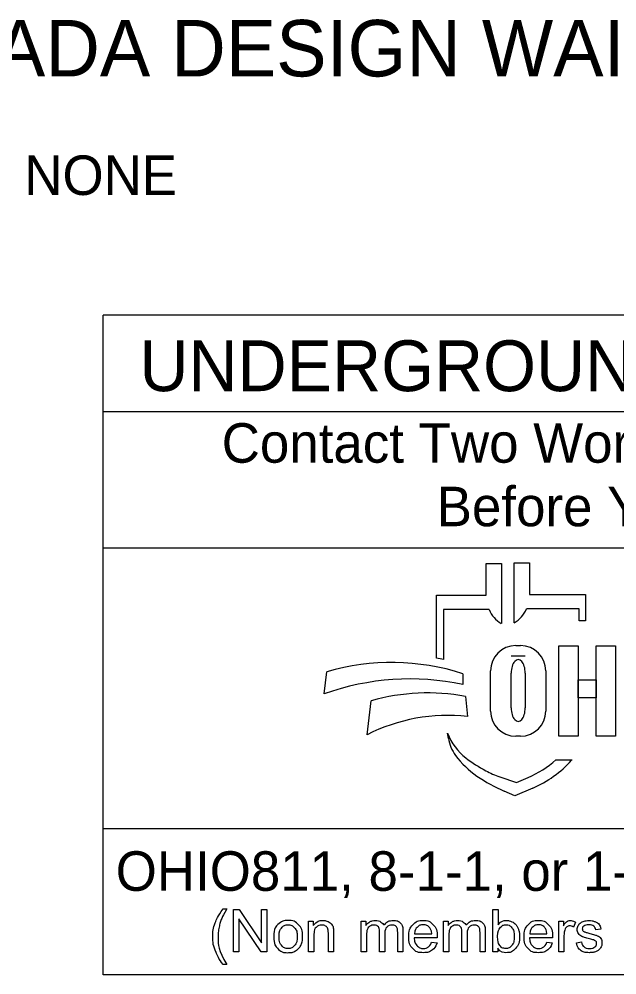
# Model space of a CAD drawing. Extents: x 0 to 34, y 0 to 22.
# Drawn here: x 2.08 to 4.196, y 2.143 to 5.529 of the extents above; entities that cross this region are included whole.
import ezdxf

# ---------------------------------------------------------------- set-up
doc = ezdxf.new("R2010")
doc.units = 0
doc.layers.add('SH_Data', color=7, linetype='Continuous')
doc.layers.add('SH_Text', color=7, linetype='Continuous')

msp = doc.modelspace()

# ---------------------------------------------------------------- linework, layer by layer
at = {"layer": 'SH_Data'}
for p, q in [((2.3775, 2.1428), (2.3775, 4.4803)), ((6.6275, 4.4803), (2.3775, 4.4803)), ((2.3775, 4.1387), (6.6275, 4.1387)), ((2.3775, 3.6553), (6.6275, 3.6553)), ((6.6275, 2.6607), (2.3775, 2.6607)), ((6.6275, 2.1428), (2.3775, 2.1428))]:
    msp.add_line(p, q, dxfattribs=at)
at = {"layer": 'SH_Text'}
for p, q in [((3.7335, 3.4883), (3.7335, 3.5998)), ((3.7335, 3.5998), (3.7872, 3.5998)), ((3.7872, 3.5998), (3.7872, 3.3877)), ((3.8329, 3.39), (3.8329, 3.6021)), ((3.8329, 3.6021), (3.8865, 3.6021)), ((3.8865, 3.6021), (3.8865, 3.4906)), ((3.5576, 3.2644), (3.5576, 3.4883)), ((3.5576, 3.4883), (3.7335, 3.4883)), ((3.8865, 3.4906), (4.0857, 3.4906)), ((4.0857, 3.4906), (4.0857, 3.3968)), ((3.5828, 3.4369), (3.5828, 3.26)), ((3.7439, 3.4369), (3.5828, 3.4369)), ((4.0625, 3.4392), (3.8761, 3.4392)), ((4.0625, 3.3968), (4.0625, 3.4392)), ((4.0857, 3.3968), (4.0625, 3.3968)), ((3.8385, 3.3091), (3.8551, 3.3091)), ((3.8718, 3.2721), (3.822, 3.2721)), ((3.7491, 3.0776), (3.7491, 3.2196)), ((3.9445, 3.2196), (3.9445, 3.0776)), ((3.1602, 3.1381), (3.1696, 3.2162)), ((3.6509, 3.2097), (3.6509, 3.1709)), ((3.822, 3.089), (3.822, 3.2114)), ((3.8718, 3.2114), (3.8718, 3.089)), ((3.6608, 3.1291), (3.6671, 3.0582)), ((3.312, 2.9936), (3.3267, 3.1137)), ((3.5997, 2.9807), (3.5967, 2.9986)), ((3.8551, 2.9882), (3.8385, 2.9882)), ((3.98, 2.9048), (4.0375, 2.9048)), ((3.7816, 2.8444), (3.841, 2.8239)), ((3.841, 2.8239), (3.8821, 2.8417)), ((3.835, 2.7769), (3.7976, 2.7934)), ((3.8983, 2.8044), (3.835, 2.7769))]:
    msp.add_line(p, q, dxfattribs=at)
for points in [[(3.991, 3.3081), (4.0589, 3.3081), (4.0589, 2.9881), (3.991, 2.9881)], [(4.1231, 3.3081), (4.1911, 3.3081), (4.1911, 2.9881), (4.1231, 2.9881)], [(4.0589, 3.1882), (4.1231, 3.1882), (4.1231, 3.1242), (4.0589, 3.1242)]]:
    msp.add_lwpolyline(points, close=True, dxfattribs=at)
for points in [[(2.8021, 2.3766), (2.8153, 2.3766)], [(2.8389, 2.2239), (2.8389, 2.3741), (2.8592, 2.3741), (2.9382, 2.2561), (2.9382, 2.3741), (2.9572, 2.3741), (2.9572, 2.2239), (2.9369, 2.2239), (2.8579, 2.3419), (2.8579, 2.2239), (2.8389, 2.2239)], [(3.7743, 2.2239), (3.7573, 2.2239), (3.7573, 2.3741), (3.7757, 2.3741), (3.7757, 2.3206)], [(3.1048, 2.2239), (3.1048, 2.3328), (3.1214, 2.3328), (3.1214, 2.3173)], [(3.2912, 2.2239), (3.2912, 2.3328), (3.3077, 2.3328), (3.3077, 2.3174)], [(3.5826, 2.2239), (3.5826, 2.3328), (3.5991, 2.3328), (3.5991, 2.3174)], [(3.9904, 2.2239), (3.9904, 2.3328), (4.007, 2.3328), (4.007, 2.3163)], [(4.0495, 2.3293), (4.043, 2.3122)], [(4.1394, 2.3046), (4.1213, 2.3022)], [(3.1233, 2.2833), (3.1233, 2.2239), (3.1048, 2.2239)], [(3.1932, 2.2908), (3.1932, 2.2239), (3.1748, 2.2239), (3.1748, 2.2901)], [(3.3097, 2.2803), (3.3097, 2.2239), (3.2912, 2.2239)], [(3.3743, 2.2871), (3.3743, 2.2239), (3.3559, 2.2239), (3.3559, 2.2946)], [(3.4388, 2.2986), (3.4388, 2.2239), (3.4203, 2.2239), (3.4203, 2.2924)], [(3.56, 2.2736), (3.4788, 2.2736)], [(3.4799, 2.2887), (3.5406, 2.2887)], [(3.601, 2.2803), (3.601, 2.2239), (3.5826, 2.2239)], [(3.6657, 2.2871), (3.6657, 2.2239), (3.6473, 2.2239), (3.6473, 2.2946)], [(3.7301, 2.2986), (3.7301, 2.2239), (3.7117, 2.2239), (3.7117, 2.2924)], [(3.968, 2.2736), (3.8868, 2.2736)], [(3.8879, 2.2887), (3.9486, 2.2887)], [(4.0088, 2.2809), (4.0088, 2.2239), (3.9904, 2.2239)], [(3.5404, 2.2591), (3.5595, 2.2567)], [(3.7743, 2.2375), (3.7743, 2.2239)], [(3.9484, 2.2591), (3.9675, 2.2567)], [(4.053, 2.2564), (4.0712, 2.2593)], [(2.8153, 2.1798), (2.8021, 2.1798)]]:
    msp.add_lwpolyline(points, dxfattribs=at)
for centre, radius, start, end in [((3.8353, 3.4736), 0.0985, 201.9296, 240.7469), ((3.7847, 3.476), 0.0985, 299.2531, 338.0704), ((3.8385, 3.2196), 0.0895, 90, 180), ((3.8551, 3.2196), 0.0895, 0, 90), ((3.4295, 2.4554), 0.8191, 79.2074, 81.0007), ((3.3997, 2.4302), 0.8191, 72.1402, 106.3144), ((3.4628, 2.2991), 0.8919, 77.8238, 109.8274), ((3.5267, 2.4094), 0.7322, 79.44, 105.8467), ((3.5987, 2.4262), 0.6357, 83.8248, 116.8021), ((3.8385, 3.0776), 0.0895, 180, 270), ((3.8551, 3.0776), 0.0895, 270, 0), ((3.7841, 3.0707), 0.2008, 201.0457, 232.5314), ((3.741, 3.0048), 0.1433, 189.6817, 216.0884), ((3.8747, 3.1022), 0.3088, 216.0884, 235.7167), ((3.9766, 3.3219), 0.5173, 232.5314, 241.794), ((3.7387, 3.1722), 0.3602, 293.4582, 312.0712), ((3.7387, 3.1722), 0.401, 293.4582, 317.8286), ((4.0412, 3.3465), 0.6044, 235.7167, 246.2325), ((3.8914, 3.1631), 0.3371, 241.794, 250.9821)]:
    msp.add_arc(centre, radius, start, end, dxfattribs=at)
for centre, start_param, end_param in [((3.8469, 3.2114), 4.712389, 7.853982), ((3.8469, 3.089), 1.570796, 4.712389)]:
    msp.add_ellipse(centre, major_axis=(0, 0.0484), ratio=0.514403, start_param=start_param, end_param=end_param, dxfattribs=at)
for points in [[(2.8021, 2.1798), (2.7869, 2.199), (2.7763, 2.2248), (2.7657, 2.2506), (2.7657, 2.2783), (2.7657, 2.3026), (2.7736, 2.325), (2.7829, 2.3509), (2.8021, 2.3766)], [(2.8153, 2.3766), (2.8029, 2.3553), (2.7989, 2.3462), (2.7927, 2.332), (2.7891, 2.3167), (2.7847, 2.2975), (2.7847, 2.2782), (2.7847, 2.2289), (2.8153, 2.1798)], [(2.9814, 2.2783), (2.9814, 2.3085), (2.9981, 2.3231), (3.0122, 2.3352), (3.0323, 2.3352), (3.0547, 2.3352), (3.069, 2.3205), (3.0832, 2.3058), (3.0832, 2.2799), (3.0832, 2.2589), (3.0769, 2.2469), (3.0706, 2.2348), (3.0586, 2.2282), (3.0466, 2.2215), (3.0323, 2.2215), (3.0095, 2.2215), (2.9954, 2.2362), (2.9814, 2.2508), (2.9814, 2.2783)], [(3.0003, 2.2783), (3.0003, 2.2574), (3.0094, 2.247), (3.0185, 2.2366), (3.0323, 2.2366), (3.046, 2.2366), (3.0551, 2.2471), (3.0642, 2.2575), (3.0642, 2.279), (3.0642, 2.2991), (3.0551, 2.3095), (3.0459, 2.3199), (3.0323, 2.3199), (3.0185, 2.3199), (3.0094, 2.3096), (3.0003, 2.2992), (3.0003, 2.2783)], [(3.1214, 2.3173), (3.1334, 2.3352), (3.156, 2.3352), (3.1659, 2.3352), (3.1741, 2.3316), (3.1823, 2.3281), (3.1864, 2.3224), (3.1905, 2.3166), (3.1922, 2.3087), (3.1932, 2.3036), (3.1932, 2.2908)], [(3.1748, 2.2901), (3.1748, 2.3013), (3.1726, 2.3069), (3.1705, 2.3125), (3.165, 2.3158), (3.1595, 2.3191), (3.1521, 2.3191), (3.1404, 2.3191), (3.1318, 2.3117), (3.1233, 2.3042), (3.1233, 2.2833)], [(3.3077, 2.3174), (3.3128, 2.3254), (3.3214, 2.3303), (3.3299, 2.3352), (3.3407, 2.3352), (3.3528, 2.3352), (3.3606, 2.3301), (3.3683, 2.3251), (3.3715, 2.3161), (3.3844, 2.3352), (3.4051, 2.3352), (3.4213, 2.3352), (3.43, 2.3262), (3.4388, 2.3172), (3.4388, 2.2986)], [(3.3559, 2.2946), (3.3559, 2.3069), (3.3514, 2.313), (3.3469, 2.3191), (3.3366, 2.3191), (3.3288, 2.3191), (3.3222, 2.315), (3.3156, 2.311), (3.3126, 2.3031), (3.3097, 2.2952), (3.3097, 2.2803)], [(3.4203, 2.2924), (3.4203, 2.3035), (3.4185, 2.3083), (3.4168, 2.3132), (3.412, 2.3162), (3.4073, 2.3191), (3.401, 2.3191), (3.3895, 2.3191), (3.3819, 2.3115), (3.3743, 2.3039), (3.3743, 2.2871)], [(3.5595, 2.2567), (3.555, 2.24), (3.5428, 2.2307), (3.5306, 2.2215), (3.5117, 2.2215), (3.4878, 2.2215), (3.4738, 2.2362), (3.4598, 2.2509), (3.4598, 2.2774), (3.4598, 2.3049), (3.474, 2.32), (3.4881, 2.3352), (3.5106, 2.3352), (3.5324, 2.3352), (3.5463, 2.3203), (3.5601, 2.3055), (3.5601, 2.2785), (3.5601, 2.2769), (3.56, 2.2736)], [(3.5406, 2.2887), (3.5394, 2.3025), (3.5337, 2.3094), (3.5249, 2.3201), (3.5108, 2.3201), (3.4981, 2.3201), (3.4894, 2.3115), (3.4808, 2.303), (3.4799, 2.2887)], [(3.5991, 2.3174), (3.6042, 2.3254), (3.6127, 2.3303), (3.6212, 2.3352), (3.6321, 2.3352), (3.6442, 2.3352), (3.6519, 2.3301), (3.6597, 2.3251), (3.6628, 2.3161), (3.6758, 2.3352), (3.6965, 2.3352), (3.7127, 2.3352), (3.7214, 2.3262), (3.7301, 2.3172), (3.7301, 2.2986)], [(3.6473, 2.2946), (3.6473, 2.3069), (3.6428, 2.313), (3.6383, 2.3191), (3.628, 2.3191), (3.6202, 2.3191), (3.6136, 2.315), (3.607, 2.311), (3.604, 2.3031), (3.601, 2.2952), (3.601, 2.2803)], [(3.7117, 2.2924), (3.7117, 2.3035), (3.7099, 2.3083), (3.7081, 2.3132), (3.7034, 2.3162), (3.6987, 2.3191), (3.6923, 2.3191), (3.6809, 2.3191), (3.6733, 2.3115), (3.6657, 2.3039), (3.6657, 2.2871)], [(3.7741, 2.2792), (3.7741, 2.2596), (3.7794, 2.2509), (3.7881, 2.2366), (3.8029, 2.2366), (3.815, 2.2366), (3.8238, 2.2471), (3.8326, 2.2576), (3.8326, 2.2784), (3.8326, 2.2998), (3.8241, 2.3099), (3.8157, 2.3201), (3.8038, 2.3201), (3.7917, 2.3201), (3.7829, 2.3096), (3.7741, 2.299), (3.7741, 2.2792)], [(3.7757, 2.3206), (3.7874, 2.3352), (3.8055, 2.3352), (3.8155, 2.3352), (3.8245, 2.3311), (3.8335, 2.3271), (3.8392, 2.3198), (3.845, 2.3124), (3.8483, 2.3021), (3.8516, 2.2918), (3.8516, 2.28), (3.8516, 2.252), (3.8378, 2.2368), (3.8239, 2.2215), (3.8046, 2.2215), (3.7853, 2.2215), (3.7743, 2.2375)], [(3.9675, 2.2567), (3.963, 2.24), (3.9508, 2.2307), (3.9386, 2.2215), (3.9196, 2.2215), (3.8958, 2.2215), (3.8818, 2.2362), (3.8678, 2.2509), (3.8678, 2.2774), (3.8678, 2.3049), (3.882, 2.32), (3.8961, 2.3352), (3.9186, 2.3352), (3.9404, 2.3352), (3.9543, 2.3203), (3.9681, 2.3055), (3.9681, 2.2785), (3.9681, 2.2769), (3.968, 2.2736)], [(3.9486, 2.2887), (3.9474, 2.3025), (3.9417, 2.3094), (3.9328, 2.3201), (3.9188, 2.3201), (3.9061, 2.3201), (3.8974, 2.3115), (3.8888, 2.303), (3.8879, 2.2887)], [(4.007, 2.3163), (4.0133, 2.3278), (4.0187, 2.3315), (4.0241, 2.3352), (4.0305, 2.3352), (4.0398, 2.3352), (4.0495, 2.3293)], [(4.043, 2.3122), (4.0363, 2.3162), (4.0295, 2.3162), (4.0235, 2.3162), (4.0187, 2.3125), (4.0139, 2.3089), (4.0119, 2.3024), (4.0088, 2.2926), (4.0088, 2.2809)], [(4.1213, 2.3022), (4.1201, 2.3106), (4.1142, 2.3153), (4.1083, 2.3201), (4.0975, 2.3201), (4.0848, 2.3201), (4.0794, 2.3159), (4.0739, 2.3116), (4.0739, 2.306), (4.0739, 2.3024), (4.0762, 2.2995), (4.0785, 2.2966), (4.0833, 2.2946), (4.086, 2.2936), (4.0996, 2.2899), (4.1192, 2.2847), (4.1269, 2.2813), (4.1347, 2.278), (4.1391, 2.2717), (4.1435, 2.2653), (4.1435, 2.2559), (4.1435, 2.2467), (4.1381, 2.2386), (4.1327, 2.2304), (4.1226, 2.226), (4.1124, 2.2215), (4.0996, 2.2215), (4.0784, 2.2215), (4.0672, 2.2303), (4.0561, 2.2391), (4.053, 2.2564)], [(4.0712, 2.2593), (4.0727, 2.2483), (4.0798, 2.2425), (4.0868, 2.2366), (4.0995, 2.2366), (4.1122, 2.2366), (4.1184, 2.2418), (4.1245, 2.247), (4.1245, 2.254), (4.1245, 2.2602), (4.1191, 2.2638), (4.1153, 2.2663), (4.1002, 2.2701), (4.0799, 2.2752), (4.072, 2.2789), (4.0642, 2.2827), (4.0601, 2.2893), (4.0561, 2.2959), (4.0561, 2.3038), (4.0561, 2.3111), (4.0594, 2.3173), (4.0628, 2.3235), (4.0685, 2.3276), (4.0728, 2.3308), (4.0803, 2.333), (4.0877, 2.3352), (4.0962, 2.3352), (4.109, 2.3352), (4.1187, 2.3315), (4.1284, 2.3278), (4.133, 2.3215), (4.1377, 2.3152), (4.1394, 2.3046)], [(3.4788, 2.2736), (3.4799, 2.2557), (3.489, 2.2462), (3.4981, 2.2366), (3.5117, 2.2366), (3.5219, 2.2366), (3.5291, 2.242), (3.5362, 2.2473), (3.5404, 2.2591)], [(3.8868, 2.2736), (3.8879, 2.2557), (3.897, 2.2462), (3.9061, 2.2366), (3.9197, 2.2366), (3.9299, 2.2366), (3.937, 2.242), (3.9442, 2.2473), (3.9484, 2.2591)]]:
    msp.add_open_spline(points, degree=3, dxfattribs=at)

# ---------------------------------------------------------------- texts
for s, height, p in [('ADA DESIGN WAIVERS', 0.2, (1.9944, 5.3256)), ('  NONE                                   ', 0.14, (1.9944, 4.9056)), ('UNDERGROUND UTILITIES', 0.18, (2.5057, 4.2106)), ('Contact Two Working Days', 0.14, (2.7972, 3.9571)), ('Before You Dig', 0.14, (3.5583, 3.7321)), ('OHIO811, 8-1-1, or 1-800-362-2764', 0.14, (2.422, 2.4406))]:
    msp.add_text(s, height=height, dxfattribs=at).set_placement(p)

doc.saveas('drawing.dxf')
